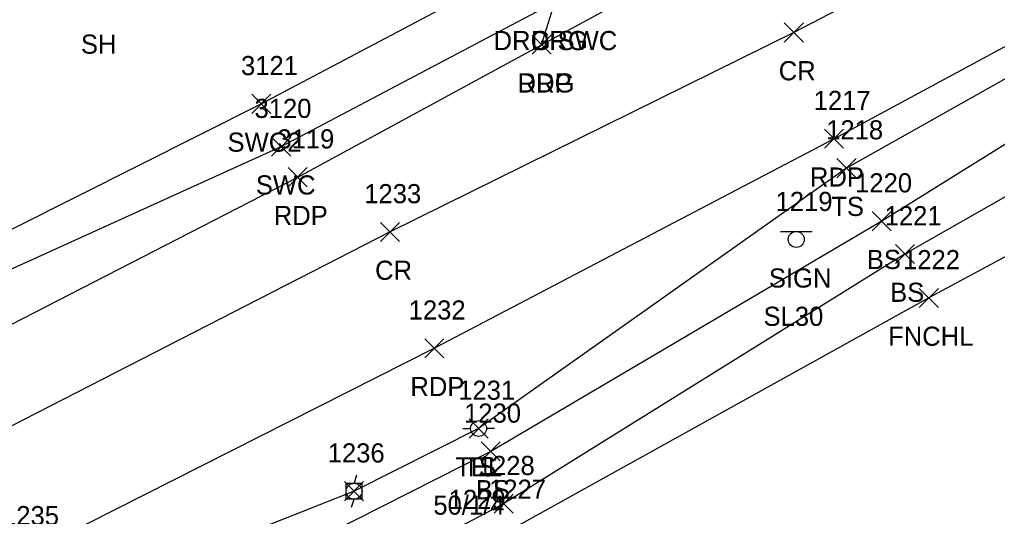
# Model space of a CAD drawing. Extents: x 1477930 to 1480780, y 774090 to 784647.
# Drawn here: x 1479474.7 to 1479576.9, y 774710.6 to 774762.5 of the extents above; entities that cross this region are included whole.
import ezdxf

# ---------------------------------------------------------------- set-up
doc = ezdxf.new("R2010")
doc.units = 0
for name, color, linetype in [('L_A', 7, 'Continuous'), ('L_I', 7, 'Continuous'), ('L_TIC', 7, 'Continuous'), ('LELB', 7, 'Continuous'), ('LFNC', 7, 'Continuous'), ('P_A', 7, 'Continuous'), ('P_I', 7, 'Continuous'), ('P_TIC', 7, 'Continuous'), ('PET', 7, 'Continuous'), ('PRC', 7, 'Continuous'), ('R_A', 7, 'Continuous'), ('R_I', 7, 'Continuous'), ('R_TIC', 7, 'Continuous'), ('RDG', 7, 'Continuous'), ('RSW', 7, 'Continuous'), ('S_A', 7, 'Continuous'), ('S_C', 7, 'Continuous'), ('S_I', 7, 'Continuous'), ('SSGN', 7, 'Continuous'), ('U_A', 7, 'Continuous'), ('U_C', 7, 'Continuous'), ('U_I', 7, 'Continuous'), ('UP', 7, 'Continuous')]:
    doc.layers.add(name, color=color, linetype=linetype)

msp = doc.modelspace()

# ---------------------------------------------------------------- linework, layer by layer
at = {"layer": 'L_TIC'}
for points in [[(1479560.12, 774745.99), (1479562.12, 774747.99)], [(1479562.12, 774745.99), (1479560.12, 774747.99)], [(1479563.8, 774740.45), (1479565.8, 774742.45)], [(1479565.8, 774740.45), (1479563.8, 774742.45)], [(1479566.24, 774737.02), (1479568.24, 774739.02)], [(1479568.24, 774737.02), (1479566.24, 774739.02)], [(1479568.72, 774732.43), (1479570.72, 774734.43)], [(1479570.72, 774732.43), (1479568.72, 774734.43)], [(1479521.68, 774718.79), (1479523.68, 774720.79)], [(1479523.68, 774718.79), (1479521.68, 774720.79)], [(1479522.94, 774716.4), (1479524.94, 774718.4)], [(1479524.94, 774716.4), (1479522.94, 774718.4)], [(1479508.66, 774712.24), (1479510.66, 774714.24)], [(1479510.66, 774712.24), (1479508.66, 774714.24)], [(1479524.29, 774710.93), (1479526.29, 774712.93)], [(1479526.29, 774710.93), (1479524.29, 774712.93)]]:
    msp.add_lwpolyline(points, dxfattribs=at)
at = {"layer": 'LELB'}
for points in [[(1479759.78, 774845.84), (1479743.76, 774848.1), (1479715.88, 774830.05), (1479665.38, 774803.72), (1479650.39, 774795.36), (1479602.85, 774770.48), (1479561.12, 774746.99), (1479522.68, 774719.79), (1479509.66, 774713.24), (1479482.17, 774702.33), (1479465.55, 774693.3), (1479450.04, 774680.68), (1479444.99, 774662.35), (1479439.28, 774645.05), (1479436.33, 774630.12), (1479434.69, 774607.73), (1479420.75, 774561.37), (1479408.24, 774515.83), (1479404.08, 774492.53), (1479401.08, 774483.2), (1479386.93, 774431.62)], [(1479759.78, 774845.84), (1479747.61, 774840.08), (1479717.72, 774826.7), (1479693.11, 774813.12), (1479667.75, 774799.87), (1479652.34, 774792.25), (1479604.7, 774766.29), (1479564.8, 774741.45), (1479523.94, 774717.4), (1479484.23, 774697.29), (1479467.35, 774689.75), (1479454.86, 774676.9), (1479444.99, 774662.35), (1479436.47, 774645.61)], [(1479755.47, 774826.43), (1479747.52, 774835), (1479732.81, 774826.8), (1479711.85, 774814.98), (1479703.35, 774801.53), (1479690.31, 774796.96), (1479675.98, 774796.31), (1479667.39, 774786.04), (1479656.48, 774787.57), (1479654.62, 774789.12), (1479607, 774760.65), (1479567.24, 774738.02), (1479525.29, 774711.93), (1479486.59, 774691.55), (1479469.23, 774685.68), (1479454.86, 774676.9)]]:
    msp.add_lwpolyline(points, dxfattribs=at)
at = {"layer": 'LFNC'}
msp.add_lwpolyline([(1479663.5, 774773.7), (1479660.34, 774780.67), (1479659.08, 774782.89), (1479609.82, 774754.99), (1479569.72, 774733.43), (1479526.46, 774709.45), (1479487.86, 774688.03), (1479452.66, 774667.9), (1479445.76, 774640.86), (1479438.34, 774612.12), (1479428.73, 774573.41), (1479420.36, 774539.52), (1479411.98, 774506.91), (1479408.88, 774492.5)], dxfattribs=at)
at = {"layer": 'P_TIC'}
for points in [[(1479554.61, 774760.16), (1479556.61, 774762.16)], [(1479556.61, 774760.16), (1479554.61, 774762.16)], [(1479528.26, 774758.88), (1479530.26, 774760.88)], [(1479530.26, 774758.88), (1479528.26, 774760.88)], [(1479558.82, 774749.06), (1479560.82, 774751.06)], [(1479560.82, 774749.06), (1479558.82, 774751.06)], [(1479502.78, 774745.04), (1479504.78, 774747.04)], [(1479504.78, 774745.04), (1479502.78, 774747.04)], [(1479512.42, 774739.32), (1479514.42, 774741.32)], [(1479514.42, 774739.32), (1479512.42, 774741.32)], [(1479517.06, 774727.17), (1479519.06, 774729.17)], [(1479519.06, 774727.17), (1479517.06, 774729.17)]]:
    msp.add_lwpolyline(points, dxfattribs=at)
at = {"layer": 'PET'}
for points in [[(1479458.85, 774725.87), (1479463.75, 774725.49), (1479503.78, 774746.04), (1479529.26, 774759.88), (1479547.26, 774769.69), (1479593.15, 774794.19), (1479638.49, 774817.33), (1479672.22, 774835.12), (1479713.57, 774857.96), (1479753.19, 774879.74), (1479794.61, 774902.46), (1479830.33, 774920.88), (1479861.74, 774937.83), (1479877.76, 774946.85), (1479905.13, 774960.92), (1479936.65, 774977.61), (1479958.81, 774989.4), (1479973, 774995.93), (1480008.35, 775014.95)], [(1479713.99, 774833.47), (1479663.95, 774806), (1479649, 774797.94), (1479602.12, 774772.9), (1479559.82, 774750.06), (1479518.06, 774728.17), (1479475.57, 774706.69), (1479465.7, 774701.25), (1479434.17, 774686.11), (1479428.66, 774666.26), (1479418.77, 774633.96), (1479413.82, 774614.69), (1479404.23, 774566.57), (1479393.7, 774517.71), (1479389.34, 774499.77)]]:
    msp.add_lwpolyline(points, dxfattribs=at)
at = {"layer": 'PRC'}
msp.add_lwpolyline([(1480015.89, 775005.87), (1479971.79, 774982.46), (1479929.14, 774959.03), (1479892.61, 774942.34), (1479860.44, 774925.31), (1479806.49, 774896.54), (1479658.45, 774815.54), (1479643.75, 774807.57), (1479597.62, 774782.97), (1479555.61, 774761.16), (1479513.42, 774740.32), (1479471, 774718.6), (1479432.73, 774701.1), (1479418.32, 774694.97), (1479344.83, 774660.92), (1479298.6, 774640.39), (1479262.12, 774624.4), (1479219.63, 774609.01), (1479186.74, 774593.83)], dxfattribs=at)
at = {"layer": 'R_TIC'}
for points in [[(1479528.26, 774758.88), (1479530.26, 774760.88)], [(1479530.26, 774758.88), (1479528.26, 774760.88)], [(1479498.97, 774752.7), (1479500.97, 774754.7)], [(1479500.97, 774752.7), (1479498.97, 774754.7)], [(1479501.04, 774748.23), (1479503.04, 774750.23)], [(1479503.04, 774748.23), (1479501.04, 774750.23)]]:
    msp.add_lwpolyline(points, dxfattribs=at)
at = {"layer": 'RDG'}
msp.add_lwpolyline([(1479529.26, 774759.88), (1479530.65, 774764.31)], dxfattribs=at)
at = {"layer": 'RSW'}
for points in [[(1479454.05, 774732.2), (1479457.36, 774735.51), (1479461.55, 774734.41), (1479499.97, 774753.7), (1479531.62, 774770.46), (1479545.78, 774777.94), (1479596.7, 774804.86), (1479626.34, 774821.05), (1479665.84, 774842.34), (1479709.72, 774866.29), (1479748.23, 774887.23), (1479790.98, 774910.55), (1479825.88, 774929.42), (1479857.89, 774946.35), (1479880.81, 774958.36), (1479898.02, 774967.81), (1479932.31, 774985.56), (1479966.42, 775003.67), (1480005.03, 775023.74)], [(1479458.85, 774725.87), (1479459.6, 774730), (1479502.04, 774749.23), (1479530.65, 774764.31), (1479546.64, 774772.58), (1479592.5, 774796.78), (1479632.83, 774818.63), (1479668.4, 774838.36), (1479711.89, 774862.21), (1479750.54, 774883.44), (1479792.95, 774906.12), (1479828.15, 774924.96), (1479859.81, 774941.82), (1479882.29, 774953.43), (1479899.45, 774962.93), (1479935.39, 774981.77), (1479958.84, 774993.68), (1479967.68, 774998.52), (1480006.53, 775018.83)]]:
    msp.add_lwpolyline(points, dxfattribs=at)
at = {"layer": 'SSGN'}
for p, q in [((1479554.22, 774740.37), (1479557.55, 774740.37)), ((1479555.87, 774739.54), (1479555.87, 774739.54))]:
    msp.add_line(p, q, dxfattribs=at)
msp.add_circle((1479555.87, 774739.54), 0.833, dxfattribs=at)
at = {"layer": 'UP'}
for p, q in [((1479521.02, 774719.79), (1479521.85, 774719.79)), ((1479522.68, 774719.79), (1479522.68, 774719.79)), ((1479524.35, 774719.79), (1479523.51, 774719.79)), ((1479523.51, 774719.79), (1479523.51, 774719.79)), ((1479524.35, 774719.79), (1479524.35, 774719.79)), ((1479509.91, 774714.9), (1479509.66, 774714.07)), ((1479508.83, 774712.4), (1479508.83, 774714.07)), ((1479508.83, 774714.07), (1479510.49, 774714.07)), ((1479510.49, 774714.07), (1479510.49, 774712.4)), ((1479509.66, 774713.24), (1479509.66, 774713.24)), ((1479510.49, 774712.4), (1479508.83, 774712.4)), ((1479509.41, 774711.57), (1479509.66, 774712.4))]:
    msp.add_line(p, q, dxfattribs=at)
for centre in [(1479522.68, 774719.79), (1479509.66, 774713.24)]:
    msp.add_circle(centre, 0.833, dxfattribs=at)

# ---------------------------------------------------------------- texts
at = {"layer": 'L_A'}
for s, p in [('SH', (1479481.12, 774758.94)), ('TS', (1479559.53, 774741.99)), ('BS', (1479563.24, 774736.45)), ('BS', (1479565.68, 774733.02)), ('FNCHL', (1479565.47, 774728.43)), ('TS', (1479521.09, 774714.79)), ('BS', (1479522.38, 774712.4))]:
    msp.add_text(s, height=2, dxfattribs=at).set_placement(p)
at = {"layer": 'L_I'}
for s, p in [('1218', (1479559, 774749.99)), ('1220', (1479562.02, 774744.45)), ('1221', (1479565.11, 774741.02)), ('1222', (1479567.03, 774736.43)), ('1231', (1479520.55, 774722.79)), ('1230', (1479521.16, 774720.4)), ('1236', (1479506.91, 774716.24)), ('1228', (1479522.59, 774714.93)), ('1227', (1479523.77, 774712.45))]:
    msp.add_text(s, height=2, dxfattribs=at).set_placement(p)
at = {"layer": 'P_A'}
for s, p in [('CR', (1479554.04, 774756.16)), ('RDP', (1479526.75, 774754.88)), ('RDP', (1479557.3, 774745.06)), ('RDP', (1479501.27, 774741.04)), ('CR', (1479511.86, 774735.32)), ('RDP', (1479515.55, 774723.17))]:
    msp.add_text(s, height=2, dxfattribs=at).set_placement(p)
at = {"layer": 'P_I'}
for s, p in [('1217', (1479557.69, 774753.06)), ('3119', (1479501.65, 774749.04)), ('1233', (1479510.73, 774743.32)), ('1232', (1479515.37, 774731.17)), ('1235', (1479472.88, 774709.69))]:
    msp.add_text(s, height=2, dxfattribs=at).set_placement(p)
at = {"layer": 'R_A'}
for s, p in [('DRG SWC', (1479524.24, 774759.31)), ('DRG', (1479528.14, 774759.31)), ('DRG', (1479526.75, 774754.88)), ('SWC2', (1479496.44, 774748.7)), ('SWC', (1479499.4, 774744.23))]:
    msp.add_text(s, height=2, dxfattribs=at).set_placement(p)
at = {"layer": 'R_I'}
for s, p in [('3121', (1479497.85, 774756.7)), ('3120', (1479499.26, 774752.23))]:
    msp.add_text(s, height=2, dxfattribs=at).set_placement(p)
at = {"layer": 'S_A'}
msp.add_text('SIGN', height=2, dxfattribs=at).set_placement((1479553.01, 774734.51))
at = {"layer": 'S_C'}
msp.add_text('SL30', height=2, dxfattribs=at).set_placement((1479552.45, 774730.51))
at = {"layer": 'S_I'}
msp.add_text('1219', height=2, dxfattribs=at).set_placement((1479553.71, 774742.51))
at = {"layer": 'U_A'}
msp.add_text('TEL', height=2, dxfattribs=at).set_placement((1479520.24, 774714.79))
at = {"layer": 'U_C'}
msp.add_text('50/1/4', height=2, dxfattribs=at).set_placement((1479517.95, 774710.79))
at = {"layer": 'U_I'}
for s, p in [('1231', (1479520.55, 774722.79)), ('1236', (1479506.91, 774716.24)), ('1229', (1479519.55, 774711.39))]:
    msp.add_text(s, height=2, dxfattribs=at).set_placement(p)

doc.saveas('drawing.dxf')
